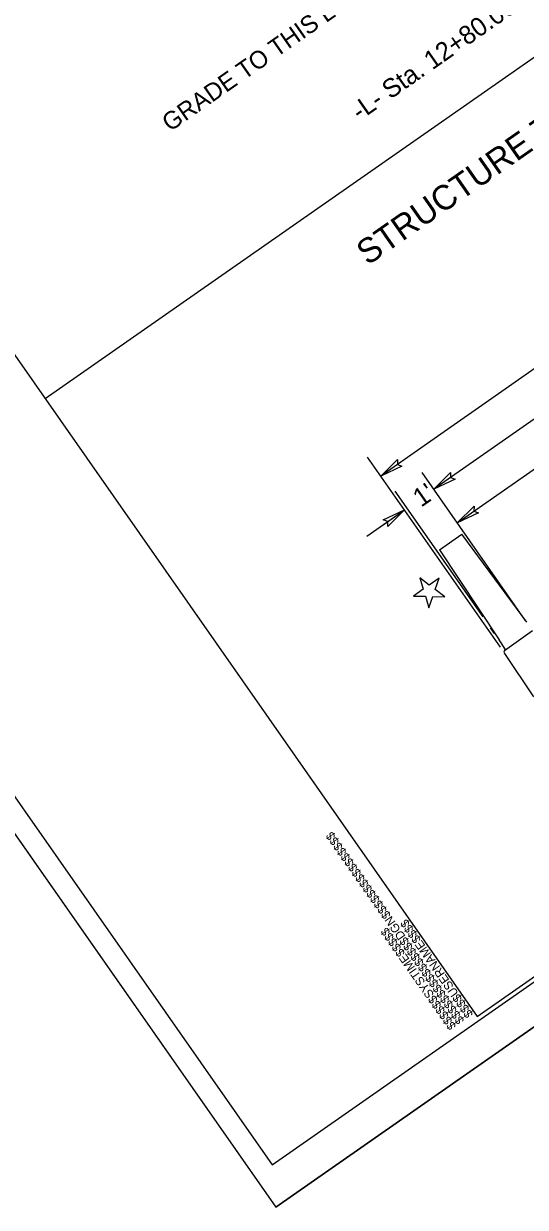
# Model space of a CAD drawing. Extents: x 1033697 to 1037131, y 657437 to 660507.
# Drawn here: x 1035508 to 1035813, y 658459 to 659179 of the extents above; entities that cross this region are included whole.
import ezdxf

# ---------------------------------------------------------------- set-up
doc = ezdxf.new("R2010")
doc.units = 0
for name, color, linetype in [('Default', 7, 'Continuous'), ('Prop Pavement Schedule Description CELL', 7, 'Continuous'), ('Prop RDY Traffic Signal CELL', 7, 'Continuous'), ('Sheet Cutting Line CELL', 7, 'Continuous'), ('Sheet Plot Border Inside CELL', 7, 'Continuous'), ('Sheet Plot Border Outside CELL', 7, 'Continuous'), ('Sheet Typical CELL', 7, 'Continuous'), ('Typical Terminator CELL', 7, 'Continuous'), ('Typical Text General CELL', 7, 'Continuous')]:
    doc.layers.add(name, color=color, linetype=linetype)

msp = doc.modelspace()

# ---------------------------------------------------------------- linework, layer by layer
at = {"layer": 'Default'}
for p, q in [((1035521.13, 658950.73), (1036750.78, 659809.79)), ((1036118.55, 659178.6), (1035725.09, 658903.6)), ((1036114.55, 659145.31), (1035757.31, 658895.62)), ((1035771.63, 658875.13), (1035950.45, 659000.11)), ((1035797.86, 658799.49), (1035717.11, 658915.01)), ((1035812.96, 658815.99), (1035750.22, 658905.76)), ((1035787.26, 658817.85), (1035733.83, 658894.3)), ((1035716.54, 658867.02), (1035739.46, 658883.04)), ((1035727.12, 658874.41), (1035738.83, 658882.59)), ((1035760.72, 658858.74), (1035774.43, 658868.32)), ((1035813.9, 658814.7), (1035774.38, 658868.29)), ((1035760.72, 658858.74), (1035797.01, 658803.9)), ((1035794.33, 658807.74), (1035791.91, 658811.2)), ((1035800.25, 658797.54), (1035817.45, 658809.56)), ((1035800.72, 658798.36), (1035798.87, 658801.13)), ((1035798.94, 658797.17), (1035798.94, 658797.17)), ((1035800.25, 658797.54), (1035800.02, 658796.39)), ((1035818.19, 658769.25), (1035800.11, 658796.26))]:
    msp.add_line(p, q, dxfattribs=at)
msp.add_lwpolyline([(1035800.94, 658798.03), (1035797.01, 658803.9)], dxfattribs=at)
at = {"layer": 'Prop RDY Traffic Signal CELL'}
msp.add_lwpolyline([(1035750.91, 658834.71), (1035744.97, 658830.55), (1035752.22, 658830.42), (1035754.34, 658823.46), (1035756.71, 658830.34), (1035763.98, 658830.21), (1035758.18, 658834.58), (1035760.55, 658841.44), (1035754.6, 658837.28), (1035748.79, 658841.66), (1035750.91, 658834.71)], dxfattribs=at)
at = {"layer": 'Sheet Cutting Line CELL'}
for p, q in [((1035661.22, 658458.77), (1037041.5, 659423.5)), ((1037041.5, 659423.5), (1035661.22, 658458.77)), ((1035031.05, 659360.38), (1035661.22, 658458.77))]:
    msp.add_line(p, q, dxfattribs=at)
at = {"layer": 'Sheet Plot Border Inside CELL'}
msp.add_lwpolyline([(1036420.5, 660304.13), (1035054.57, 659349.42), (1035659.01, 658484.62), (1037024.95, 659439.32)], close=True, dxfattribs=at)
at = {"layer": 'Sheet Plot Border Outside CELL'}
msp.add_lwpolyline([(1036411.33, 660325.1), (1035031.05, 659360.38), (1035661.22, 658458.77), (1037041.5, 659423.5)], close=True, dxfattribs=at)
at = {"layer": 'Sheet Typical CELL'}
msp.add_line((1035783.78, 658574.94), (1035783.78, 658574.94), dxfattribs=at)
msp.add_line((1035783.78, 658574.94), (1035783.78, 658574.94), dxfattribs=at)
msp.add_line((1035783.78, 658574.94), (1035783.78, 658574.94), dxfattribs=at)
msp.add_line((1035783.78, 658574.94), (1035783.78, 658574.94), dxfattribs=at)
msp.add_line((1035783.78, 658574.94), (1035783.78, 658574.94), dxfattribs=at)
msp.add_line((1035783.78, 658574.94), (1035783.78, 658574.94), dxfattribs=at)
msp.add_lwpolyline([(1036411.72, 660294.87), (1035182.26, 659435.56), (1035783.78, 658574.94), (1037013.24, 659434.25)], close=True, dxfattribs=at)
at = {"layer": 'Typical Terminator CELL'}
for points in [[(1035738, 658909.67), (1035725.09, 658903.6), (1035735.25, 658913.75), (1035735.21, 658910.67)], [(1035770.27, 658901.61), (1035757.36, 658895.55), (1035767.52, 658905.69), (1035767.47, 658902.62)], [(1035784.54, 658881.19), (1035771.63, 658875.13), (1035781.79, 658885.27), (1035781.75, 658882.2)], [(1035726.55, 658876.97), (1035739.46, 658883.04), (1035729.3, 658872.89), (1035729.34, 658875.97)]]:
    msp.add_lwpolyline(points, close=True, dxfattribs=at)

# ---------------------------------------------------------------- texts
at = {"layer": 'Default'}
msp.add_text("1'", height=11.25, rotation=34.95111, dxfattribs=at).set_placement((1035749.67, 658884.31))
at = {"layer": 'Prop Pavement Schedule Description CELL'}
msp.add_text('STRUCTURE TYPICAL SECTION', height=15, rotation=34.93895, dxfattribs=at).set_placement((1035717.16, 659031.37))
at = {"layer": 'Sheet Typical CELL'}
for s, p in [('$$$$$$$$$$$$$$$$DGN$$$$$$$$$$$$$$$$', (1035776.16, 658572.49)), ('$$$$USERNAME$$$$', (1035781.54, 658576.27)), ('$$$$$$SYSTIME$$$$$', (1035771.2, 658569.02))]:
    msp.add_text(s, height=5.25, rotation=124.95116, dxfattribs=at).set_placement(p)
at = {"layer": 'Typical Text General CELL'}
for s, height, p in [('-L- Sta. 12+80.00 to Sta. 14+41.81 (BEGIN BRIDGE)', 11.3295, (1035712.27, 659119.44)), ('GRADE TO THIS LINE', 10.742, (1035596.95, 659112.73))]:
    msp.add_text(s, height=height, rotation=34.93895, dxfattribs=at).set_placement(p)

doc.saveas('drawing.dxf')
